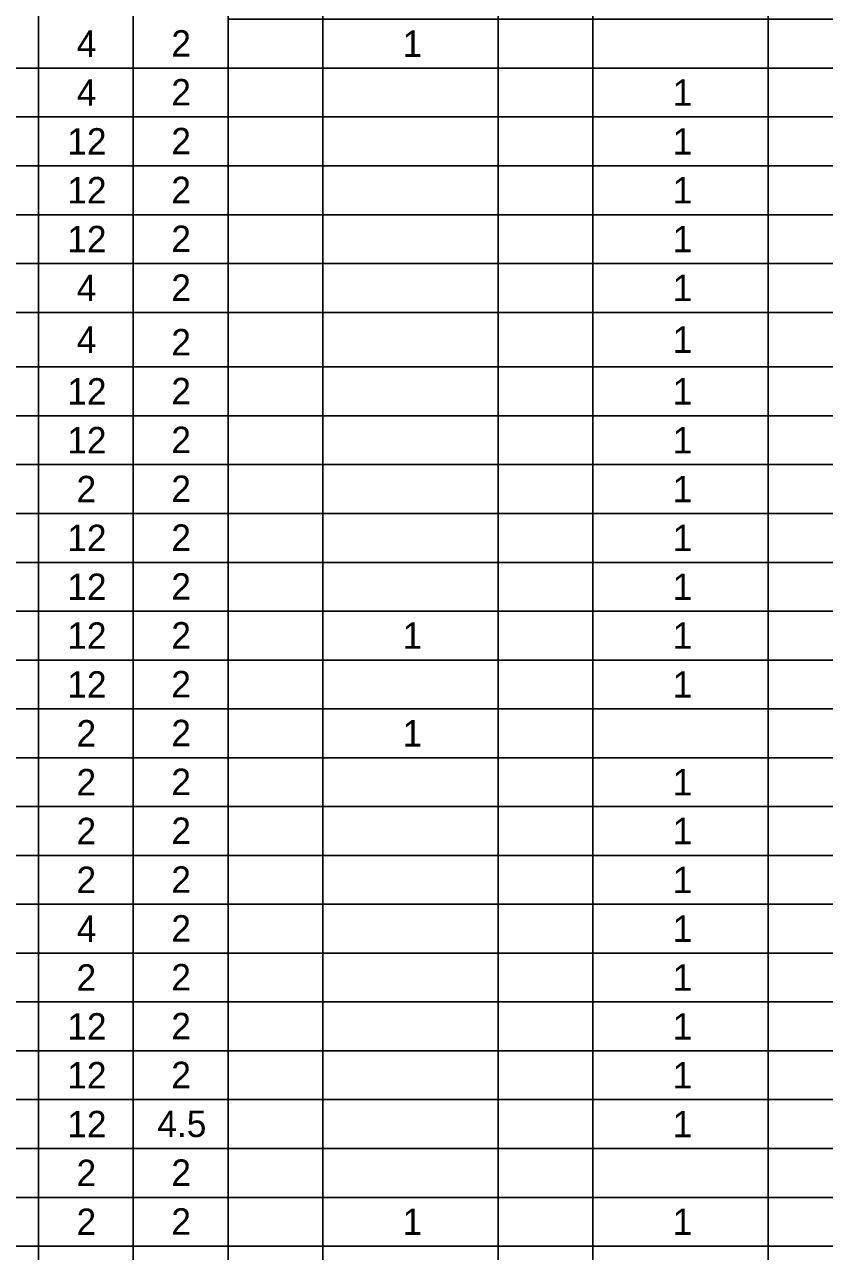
# Model space of a CAD drawing. Extents: x 0 to 34, y 0 to 22.
# Drawn here: x 8.44 to 12.61, y 4.54 to 10.94 of the extents above; entities that cross this region are included whole.
import ezdxf

# ---------------------------------------------------------------- set-up
doc = ezdxf.new("R2010")
doc.units = 0
doc.layers.add('Default', color=7, linetype='Continuous')

msp = doc.modelspace()

# ---------------------------------------------------------------- linework, layer by layer
at = {"layer": 'Default'}
for p, q in [((8.5114, 21.2135), (8.5114, 1.2485)), ((9.0064, 21.2135), (9.0064, 1.2485)), ((9.5014, 21.2135), (9.5014, 1.2485)), ((9.9964, 18.9335), (9.9964, 1.2485)), ((10.9114, 18.9335), (10.9114, 1.2485)), ((11.4064, 18.9335), (11.4064, 1.2485)), ((12.3214, 18.9335), (12.3214, 1.2485)), ((4.7014, 10.7135), (28.7614, 10.7135)), ((4.7014, 10.4585), (28.7614, 10.4585)), ((4.7014, 10.2035), (28.7614, 10.2035)), ((4.7014, 9.9485), (28.7614, 9.9485)), ((4.7014, 9.6935), (28.7614, 9.6935)), ((4.7014, 9.4385), (28.7614, 9.4385)), ((4.7014, 9.1535), (28.7614, 9.1535)), ((4.7014, 8.8985), (28.7614, 8.8985)), ((4.7014, 8.6435), (28.7614, 8.6435)), ((4.7014, 8.3885), (28.7614, 8.3885)), ((4.7014, 8.1335), (28.7614, 8.1335)), ((4.7014, 7.8785), (28.7614, 7.8785)), ((4.7014, 7.6235), (28.7614, 7.6235)), ((4.7014, 7.3685), (28.7614, 7.3685)), ((4.7014, 7.1135), (28.7614, 7.1135)), ((4.7014, 6.8585), (28.7614, 6.8585)), ((4.7014, 6.6035), (28.7614, 6.6035)), ((4.7014, 6.3485), (28.7614, 6.3485)), ((4.7014, 6.0935), (28.7614, 6.0935)), ((4.7014, 5.8385), (28.7614, 5.8385)), ((4.7014, 5.5835), (28.7614, 5.5835)), ((4.7014, 5.3285), (28.7614, 5.3285)), ((4.7014, 5.0735), (28.7614, 5.0735)), ((4.7014, 4.8185), (28.7614, 4.8185)), ((4.7014, 4.5635), (28.7614, 4.5635))]:
    msp.add_line(p, q, dxfattribs=at)
for points in [[(9.5014, 10.9685), (9.9964, 10.9685), (9.9964, 10.7135), (9.5014, 10.7135)], [(9.9964, 10.9685), (10.9114, 10.9685), (10.9114, 10.7135), (9.9964, 10.7135)], [(10.9114, 10.9685), (11.4064, 10.9685), (11.4064, 10.7135), (10.9114, 10.7135)], [(11.4064, 10.9685), (12.3214, 10.9685), (12.3214, 10.7135), (11.4064, 10.7135)], [(12.3214, 10.9685), (12.8164, 10.9685), (12.8164, 10.7135), (12.3214, 10.7135)], [(8.5114, 10.7135), (9.0064, 10.7135), (9.0064, 10.4585), (8.5114, 10.4585)], [(9.5014, 10.7135), (9.9964, 10.7135), (9.9964, 10.4585), (9.5014, 10.4585)], [(9.9964, 10.7135), (10.9114, 10.7135), (10.9114, 10.4585), (9.9964, 10.4585)], [(10.9114, 10.7135), (11.4064, 10.7135), (11.4064, 10.4585), (10.9114, 10.4585)], [(11.4064, 10.7135), (12.3214, 10.7135), (12.3214, 10.4585), (11.4064, 10.4585)], [(12.3214, 10.7135), (12.8164, 10.7135), (12.8164, 10.4585), (12.3214, 10.4585)], [(8.5114, 10.4585), (9.0064, 10.4585), (9.0064, 10.2035), (8.5114, 10.2035)], [(9.5014, 10.4585), (9.9964, 10.4585), (9.9964, 10.2035), (9.5014, 10.2035)], [(9.9964, 10.4585), (10.9114, 10.4585), (10.9114, 10.2035), (9.9964, 10.2035)], [(10.9114, 10.4585), (11.4064, 10.4585), (11.4064, 10.2035), (10.9114, 10.2035)], [(11.4064, 10.4585), (12.3214, 10.4585), (12.3214, 10.2035), (11.4064, 10.2035)], [(12.3214, 10.4585), (12.8164, 10.4585), (12.8164, 10.2035), (12.3214, 10.2035)], [(8.5114, 10.2035), (9.0064, 10.2035), (9.0064, 9.9485), (8.5114, 9.9485)], [(9.5014, 10.2035), (9.9964, 10.2035), (9.9964, 9.9485), (9.5014, 9.9485)], [(9.9964, 10.2035), (10.9114, 10.2035), (10.9114, 9.9485), (9.9964, 9.9485)], [(10.9114, 10.2035), (11.4064, 10.2035), (11.4064, 9.9485), (10.9114, 9.9485)], [(11.4064, 10.2035), (12.3214, 10.2035), (12.3214, 9.9485), (11.4064, 9.9485)], [(12.3214, 10.2035), (12.8164, 10.2035), (12.8164, 9.9485), (12.3214, 9.9485)], [(8.5114, 9.9485), (9.0064, 9.9485), (9.0064, 9.6935), (8.5114, 9.6935)], [(9.5014, 9.9485), (9.9964, 9.9485), (9.9964, 9.6935), (9.5014, 9.6935)], [(9.9964, 9.9485), (10.9114, 9.9485), (10.9114, 9.6935), (9.9964, 9.6935)], [(10.9114, 9.9485), (11.4064, 9.9485), (11.4064, 9.6935), (10.9114, 9.6935)], [(11.4064, 9.9485), (12.3214, 9.9485), (12.3214, 9.6935), (11.4064, 9.6935)], [(12.3214, 9.9485), (12.8164, 9.9485), (12.8164, 9.6935), (12.3214, 9.6935)], [(8.5114, 9.6935), (9.0064, 9.6935), (9.0064, 9.4385), (8.5114, 9.4385)], [(9.5014, 9.6935), (9.9964, 9.6935), (9.9964, 9.4385), (9.5014, 9.4385)], [(9.9964, 9.6935), (10.9114, 9.6935), (10.9114, 9.4385), (9.9964, 9.4385)], [(10.9114, 9.6935), (11.4064, 9.6935), (11.4064, 9.4385), (10.9114, 9.4385)], [(11.4064, 9.6935), (12.3214, 9.6935), (12.3214, 9.4385), (11.4064, 9.4385)], [(12.3214, 9.6935), (12.8164, 9.6935), (12.8164, 9.4385), (12.3214, 9.4385)], [(8.5114, 9.4385), (9.0064, 9.4385), (9.0064, 9.1535), (8.5114, 9.1535)], [(9.5014, 9.4385), (9.9964, 9.4385), (9.9964, 9.1535), (9.5014, 9.1535)], [(9.9964, 9.4385), (10.9114, 9.4385), (10.9114, 9.1535), (9.9964, 9.1535)], [(10.9114, 9.4385), (11.4064, 9.4385), (11.4064, 9.1535), (10.9114, 9.1535)], [(11.4064, 9.4385), (12.3214, 9.4385), (12.3214, 9.1535), (11.4064, 9.1535)], [(12.3214, 9.4385), (12.8164, 9.4385), (12.8164, 9.1535), (12.3214, 9.1535)], [(9.5014, 9.1535), (9.9964, 9.1535), (9.9964, 8.8985), (9.5014, 8.8985)], [(9.9964, 9.1535), (10.9114, 9.1535), (10.9114, 8.8985), (9.9964, 8.8985)], [(10.9114, 9.1535), (11.4064, 9.1535), (11.4064, 8.8985), (10.9114, 8.8985)], [(11.4064, 9.1535), (12.3214, 9.1535), (12.3214, 8.8985), (11.4064, 8.8985)], [(12.3214, 9.1535), (12.8164, 9.1535), (12.8164, 8.8985), (12.3214, 8.8985)], [(9.5014, 8.8985), (9.9964, 8.8985), (9.9964, 8.6435), (9.5014, 8.6435)], [(9.9964, 8.8985), (10.9114, 8.8985), (10.9114, 8.6435), (9.9964, 8.6435)], [(10.9114, 8.8985), (11.4064, 8.8985), (11.4064, 8.6435), (10.9114, 8.6435)], [(11.4064, 8.8985), (12.3214, 8.8985), (12.3214, 8.6435), (11.4064, 8.6435)], [(12.3214, 8.8985), (12.8164, 8.8985), (12.8164, 8.6435), (12.3214, 8.6435)], [(8.5114, 8.6435), (9.0064, 8.6435), (9.0064, 8.3885), (8.5114, 8.3885)], [(9.5014, 8.6435), (9.9964, 8.6435), (9.9964, 8.3885), (9.5014, 8.3885)], [(9.9964, 8.6435), (10.9114, 8.6435), (10.9114, 8.3885), (9.9964, 8.3885)], [(10.9114, 8.6435), (11.4064, 8.6435), (11.4064, 8.3885), (10.9114, 8.3885)], [(11.4064, 8.6435), (12.3214, 8.6435), (12.3214, 8.3885), (11.4064, 8.3885)], [(12.3214, 8.6435), (12.8164, 8.6435), (12.8164, 8.3885), (12.3214, 8.3885)], [(8.5114, 8.3885), (9.0064, 8.3885), (9.0064, 8.1335), (8.5114, 8.1335)], [(9.5014, 8.3885), (9.9964, 8.3885), (9.9964, 8.1335), (9.5014, 8.1335)], [(9.9964, 8.3885), (10.9114, 8.3885), (10.9114, 8.1335), (9.9964, 8.1335)], [(10.9114, 8.3885), (11.4064, 8.3885), (11.4064, 8.1335), (10.9114, 8.1335)], [(11.4064, 8.3885), (12.3214, 8.3885), (12.3214, 8.1335), (11.4064, 8.1335)], [(12.3214, 8.3885), (12.8164, 8.3885), (12.8164, 8.1335), (12.3214, 8.1335)], [(8.5114, 8.1335), (9.0064, 8.1335), (9.0064, 7.8785), (8.5114, 7.8785)], [(9.5014, 8.1335), (9.9964, 8.1335), (9.9964, 7.8785), (9.5014, 7.8785)], [(9.9964, 8.1335), (10.9114, 8.1335), (10.9114, 7.8785), (9.9964, 7.8785)], [(10.9114, 8.1335), (11.4064, 8.1335), (11.4064, 7.8785), (10.9114, 7.8785)], [(11.4064, 8.1335), (12.3214, 8.1335), (12.3214, 7.8785), (11.4064, 7.8785)], [(12.3214, 8.1335), (12.8164, 8.1335), (12.8164, 7.8785), (12.3214, 7.8785)], [(8.5114, 7.8785), (9.0064, 7.8785), (9.0064, 7.6235), (8.5114, 7.6235)], [(9.5014, 7.8785), (9.9964, 7.8785), (9.9964, 7.6235), (9.5014, 7.6235)], [(9.9964, 7.8785), (10.9114, 7.8785), (10.9114, 7.6235), (9.9964, 7.6235)], [(10.9114, 7.8785), (11.4064, 7.8785), (11.4064, 7.6235), (10.9114, 7.6235)], [(11.4064, 7.8785), (12.3214, 7.8785), (12.3214, 7.6235), (11.4064, 7.6235)], [(12.3214, 7.8785), (12.8164, 7.8785), (12.8164, 7.6235), (12.3214, 7.6235)], [(8.5114, 7.6235), (9.0064, 7.6235), (9.0064, 7.3685), (8.5114, 7.3685)], [(9.5014, 7.6235), (9.9964, 7.6235), (9.9964, 7.3685), (9.5014, 7.3685)], [(9.9964, 7.6235), (10.9114, 7.6235), (10.9114, 7.3685), (9.9964, 7.3685)], [(10.9114, 7.6235), (11.4064, 7.6235), (11.4064, 7.3685), (10.9114, 7.3685)], [(11.4064, 7.6235), (12.3214, 7.6235), (12.3214, 7.3685), (11.4064, 7.3685)], [(12.3214, 7.6235), (12.8164, 7.6235), (12.8164, 7.3685), (12.3214, 7.3685)], [(8.5114, 7.3685), (9.0064, 7.3685), (9.0064, 7.1135), (8.5114, 7.1135)], [(9.5014, 7.3685), (9.9964, 7.3685), (9.9964, 7.1135), (9.5014, 7.1135)], [(9.9964, 7.3685), (10.9114, 7.3685), (10.9114, 7.1135), (9.9964, 7.1135)], [(10.9114, 7.3685), (11.4064, 7.3685), (11.4064, 7.1135), (10.9114, 7.1135)], [(11.4064, 7.3685), (12.3214, 7.3685), (12.3214, 7.1135), (11.4064, 7.1135)], [(12.3214, 7.3685), (12.8164, 7.3685), (12.8164, 7.1135), (12.3214, 7.1135)], [(8.5114, 7.1135), (9.0064, 7.1135), (9.0064, 6.8585), (8.5114, 6.8585)], [(9.5014, 7.1135), (9.9964, 7.1135), (9.9964, 6.8585), (9.5014, 6.8585)], [(9.9964, 7.1135), (10.9114, 7.1135), (10.9114, 6.8585), (9.9964, 6.8585)], [(10.9114, 7.1135), (11.4064, 7.1135), (11.4064, 6.8585), (10.9114, 6.8585)], [(11.4064, 7.1135), (12.3214, 7.1135), (12.3214, 6.8585), (11.4064, 6.8585)], [(12.3214, 7.1135), (12.8164, 7.1135), (12.8164, 6.8585), (12.3214, 6.8585)], [(8.5114, 6.8585), (9.0064, 6.8585), (9.0064, 6.6035), (8.5114, 6.6035)], [(9.5014, 6.8585), (9.9964, 6.8585), (9.9964, 6.6035), (9.5014, 6.6035)], [(9.9964, 6.8585), (10.9114, 6.8585), (10.9114, 6.6035), (9.9964, 6.6035)], [(10.9114, 6.8585), (11.4064, 6.8585), (11.4064, 6.6035), (10.9114, 6.6035)], [(11.4064, 6.8585), (12.3214, 6.8585), (12.3214, 6.6035), (11.4064, 6.6035)], [(12.3214, 6.8585), (12.8164, 6.8585), (12.8164, 6.6035), (12.3214, 6.6035)], [(8.5114, 6.6035), (9.0064, 6.6035), (9.0064, 6.3485), (8.5114, 6.3485)], [(9.5014, 6.6035), (9.9964, 6.6035), (9.9964, 6.3485), (9.5014, 6.3485)], [(9.9964, 6.6035), (10.9114, 6.6035), (10.9114, 6.3485), (9.9964, 6.3485)], [(10.9114, 6.6035), (11.4064, 6.6035), (11.4064, 6.3485), (10.9114, 6.3485)], [(11.4064, 6.6035), (12.3214, 6.6035), (12.3214, 6.3485), (11.4064, 6.3485)], [(12.3214, 6.6035), (12.8164, 6.6035), (12.8164, 6.3485), (12.3214, 6.3485)], [(8.5114, 6.3485), (9.0064, 6.3485), (9.0064, 6.0935), (8.5114, 6.0935)], [(9.5014, 6.3485), (9.9964, 6.3485), (9.9964, 6.0935), (9.5014, 6.0935)], [(9.9964, 6.3485), (10.9114, 6.3485), (10.9114, 6.0935), (9.9964, 6.0935)], [(10.9114, 6.3485), (11.4064, 6.3485), (11.4064, 6.0935), (10.9114, 6.0935)], [(11.4064, 6.3485), (12.3214, 6.3485), (12.3214, 6.0935), (11.4064, 6.0935)], [(12.3214, 6.3485), (12.8164, 6.3485), (12.8164, 6.0935), (12.3214, 6.0935)], [(8.5114, 6.0935), (9.0064, 6.0935), (9.0064, 5.8385), (8.5114, 5.8385)], [(9.5014, 6.0935), (9.9964, 6.0935), (9.9964, 5.8385), (9.5014, 5.8385)], [(9.9964, 6.0935), (10.9114, 6.0935), (10.9114, 5.8385), (9.9964, 5.8385)], [(10.9114, 6.0935), (11.4064, 6.0935), (11.4064, 5.8385), (10.9114, 5.8385)], [(11.4064, 6.0935), (12.3214, 6.0935), (12.3214, 5.8385), (11.4064, 5.8385)], [(12.3214, 6.0935), (12.8164, 6.0935), (12.8164, 5.8385), (12.3214, 5.8385)], [(8.5114, 5.8385), (9.0064, 5.8385), (9.0064, 5.5835), (8.5114, 5.5835)], [(9.5014, 5.8385), (9.9964, 5.8385), (9.9964, 5.5835), (9.5014, 5.5835)], [(9.9964, 5.8385), (10.9114, 5.8385), (10.9114, 5.5835), (9.9964, 5.5835)], [(10.9114, 5.8385), (11.4064, 5.8385), (11.4064, 5.5835), (10.9114, 5.5835)], [(11.4064, 5.8385), (12.3214, 5.8385), (12.3214, 5.5835), (11.4064, 5.5835)], [(12.3214, 5.8385), (12.8164, 5.8385), (12.8164, 5.5835), (12.3214, 5.5835)], [(8.5114, 5.5835), (9.0064, 5.5835), (9.0064, 5.3285), (8.5114, 5.3285)], [(9.5014, 5.5835), (9.9964, 5.5835), (9.9964, 5.3285), (9.5014, 5.3285)], [(9.9964, 5.5835), (10.9114, 5.5835), (10.9114, 5.3285), (9.9964, 5.3285)], [(10.9114, 5.5835), (11.4064, 5.5835), (11.4064, 5.3285), (10.9114, 5.3285)], [(11.4064, 5.5835), (12.3214, 5.5835), (12.3214, 5.3285), (11.4064, 5.3285)], [(12.3214, 5.5835), (12.8164, 5.5835), (12.8164, 5.3285), (12.3214, 5.3285)], [(8.5114, 5.3285), (9.0064, 5.3285), (9.0064, 5.0735), (8.5114, 5.0735)], [(9.5014, 5.3285), (9.9964, 5.3285), (9.9964, 5.0735), (9.5014, 5.0735)], [(9.9964, 5.3285), (10.9114, 5.3285), (10.9114, 5.0735), (9.9964, 5.0735)], [(10.9114, 5.3285), (11.4064, 5.3285), (11.4064, 5.0735), (10.9114, 5.0735)], [(11.4064, 5.3285), (12.3214, 5.3285), (12.3214, 5.0735), (11.4064, 5.0735)], [(12.3214, 5.3285), (12.8164, 5.3285), (12.8164, 5.0735), (12.3214, 5.0735)], [(8.5114, 5.0735), (9.0064, 5.0735), (9.0064, 4.8185), (8.5114, 4.8185)], [(9.5014, 5.0735), (9.9964, 5.0735), (9.9964, 4.8185), (9.5014, 4.8185)], [(9.9964, 5.0735), (10.9114, 5.0735), (10.9114, 4.8185), (9.9964, 4.8185)], [(10.9114, 5.0735), (11.4064, 5.0735), (11.4064, 4.8185), (10.9114, 4.8185)], [(11.4064, 5.0735), (12.3214, 5.0735), (12.3214, 4.8185), (11.4064, 4.8185)], [(12.3214, 5.0735), (12.8164, 5.0735), (12.8164, 4.8185), (12.3214, 4.8185)], [(8.5114, 4.8185), (9.0064, 4.8185), (9.0064, 4.5635), (8.5114, 4.5635)], [(9.5014, 4.8185), (9.9964, 4.8185), (9.9964, 4.5635), (9.5014, 4.5635)], [(9.9964, 4.8185), (10.9114, 4.8185), (10.9114, 4.5635), (9.9964, 4.5635)], [(10.9114, 4.8185), (11.4064, 4.8185), (11.4064, 4.5635), (10.9114, 4.5635)], [(11.4064, 4.8185), (12.3214, 4.8185), (12.3214, 4.5635), (11.4064, 4.5635)], [(12.3214, 4.8185), (12.8164, 4.8185), (12.8164, 4.5635), (12.3214, 4.5635)], [(9.5014, 4.5635), (9.9964, 4.5635), (9.9964, 4.3085), (9.5014, 4.3085)], [(9.9964, 4.5635), (10.9114, 4.5635), (10.9114, 4.3085), (9.9964, 4.3085)], [(10.9114, 4.5635), (11.4064, 4.5635), (11.4064, 4.3085), (10.9114, 4.3085)], [(11.4064, 4.5635), (12.3214, 4.5635), (12.3214, 4.3085), (11.4064, 4.3085)], [(12.3214, 4.5635), (12.8164, 4.5635), (12.8164, 4.3085), (12.3214, 4.3085)]]:
    msp.add_lwpolyline(points, close=True, dxfattribs=at)

# ---------------------------------------------------------------- texts
for s, p in [('4', (8.7117, 10.772)), ('2', (9.2052, 10.7735)), ('1', (10.4124, 10.772)), ('4', (8.7117, 10.517)), ('2', (9.2052, 10.5185)), ('1', (11.8224, 10.517)), ('12', (8.6619, 10.262)), ('2', (9.2052, 10.2635)), ('1', (11.8224, 10.262)), ('12', (8.6619, 10.007)), ('2', (9.2052, 10.0085)), ('1', (11.8224, 10.007)), ('12', (8.6619, 9.752)), ('2', (9.2052, 9.7535)), ('1', (11.8224, 9.752)), ('4', (8.7117, 9.497)), ('2', (9.2052, 9.4985)), ('1', (11.8224, 9.497)), ('4', (8.7117, 9.227)), ('2', (9.2052, 9.2135)), ('1', (11.8224, 9.227)), ('12', (8.6619, 8.957)), ('2', (9.2052, 8.9585)), ('1', (11.8224, 8.957)), ('12', (8.6619, 8.702)), ('2', (9.2052, 8.7035)), ('1', (11.8224, 8.702)), ('2', (8.7102, 8.447)), ('2', (9.2052, 8.4485)), ('1', (11.8224, 8.447)), ('12', (8.6619, 8.192)), ('2', (9.2052, 8.1935)), ('1', (11.8224, 8.192)), ('12', (8.6619, 7.937)), ('2', (9.2052, 7.9385)), ('1', (11.8224, 7.937)), ('12', (8.6619, 7.682)), ('2', (9.2052, 7.6835)), ('1', (10.4124, 7.682)), ('1', (11.8224, 7.682)), ('12', (8.6619, 7.427)), ('2', (9.2052, 7.4285)), ('1', (11.8224, 7.427)), ('2', (8.7102, 7.172)), ('2', (9.2052, 7.1735)), ('1', (10.4124, 7.172)), ('2', (8.7102, 6.917)), ('2', (9.2052, 6.9185)), ('1', (11.8224, 6.917)), ('2', (8.7102, 6.662)), ('2', (9.2052, 6.6635)), ('1', (11.8224, 6.662)), ('2', (8.7102, 6.407)), ('2', (9.2052, 6.4085)), ('1', (11.8224, 6.407)), ('4', (8.7117, 6.152)), ('2', (9.2052, 6.1535)), ('1', (11.8224, 6.152)), ('2', (8.7102, 5.897)), ('2', (9.2052, 5.8985)), ('1', (11.8224, 5.897)), ('12', (8.6619, 5.642)), ('2', (9.2052, 5.6435)), ('1', (11.8224, 5.642)), ('12', (8.6619, 5.387)), ('2', (9.2052, 5.3885)), ('1', (11.8224, 5.387)), ('12', (8.6619, 5.132)), ('4.5', (9.1319, 5.1335)), ('1', (11.8224, 5.132)), ('2', (8.7102, 4.877)), ('2', (9.2052, 4.8785)), ('2', (8.7102, 4.622)), ('2', (9.2052, 4.6235)), ('1', (10.4124, 4.622)), ('1', (11.8224, 4.622))]:
    msp.add_text(s, height=0.138, dxfattribs=at).set_placement(p)

doc.saveas('drawing.dxf')
